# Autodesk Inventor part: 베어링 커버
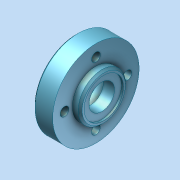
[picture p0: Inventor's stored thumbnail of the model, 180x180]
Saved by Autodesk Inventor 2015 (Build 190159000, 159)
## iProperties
Created: 2024-06
Part Number: 베어링 커버
Material: 일반
Document SubType Name: Modeling
Designer: Administrator
Density: 1 g/cm^3
Appearance: 기본값
Author: Administrator
Author: jhkim
Creation Date: 2024-05-29
Sending System: Autodesk Inventor 2025
Preprocessor: ST-DEVELOPER v20
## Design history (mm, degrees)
node "베어링 커버1"
node "솔리드1"
node "기준1"
